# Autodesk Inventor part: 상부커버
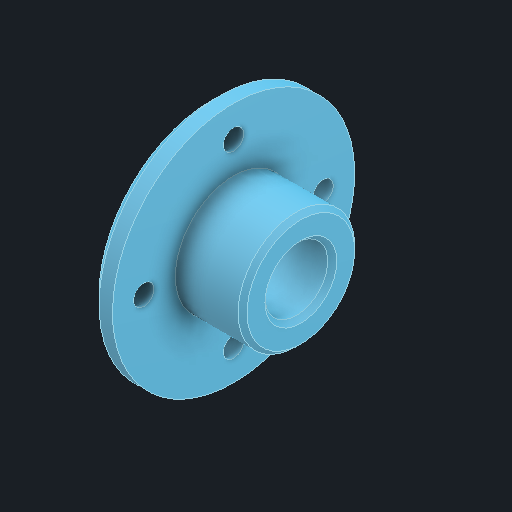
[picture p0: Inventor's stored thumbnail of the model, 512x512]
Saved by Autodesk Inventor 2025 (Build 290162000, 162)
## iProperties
Created: 2025-08
Part Number: 상부커버
Material: 알루미늄 6061
Document SubType Name: Modeling
Designer: infra005
Density: 2.71 g/cm^3
Appearance: 기본값
Author: jhkim
Sending System: Autodesk Inventor 2026
Preprocessor: ST-DEVELOPER v20.1
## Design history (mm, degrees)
feature "솔리드1"
node "솔리드2"
